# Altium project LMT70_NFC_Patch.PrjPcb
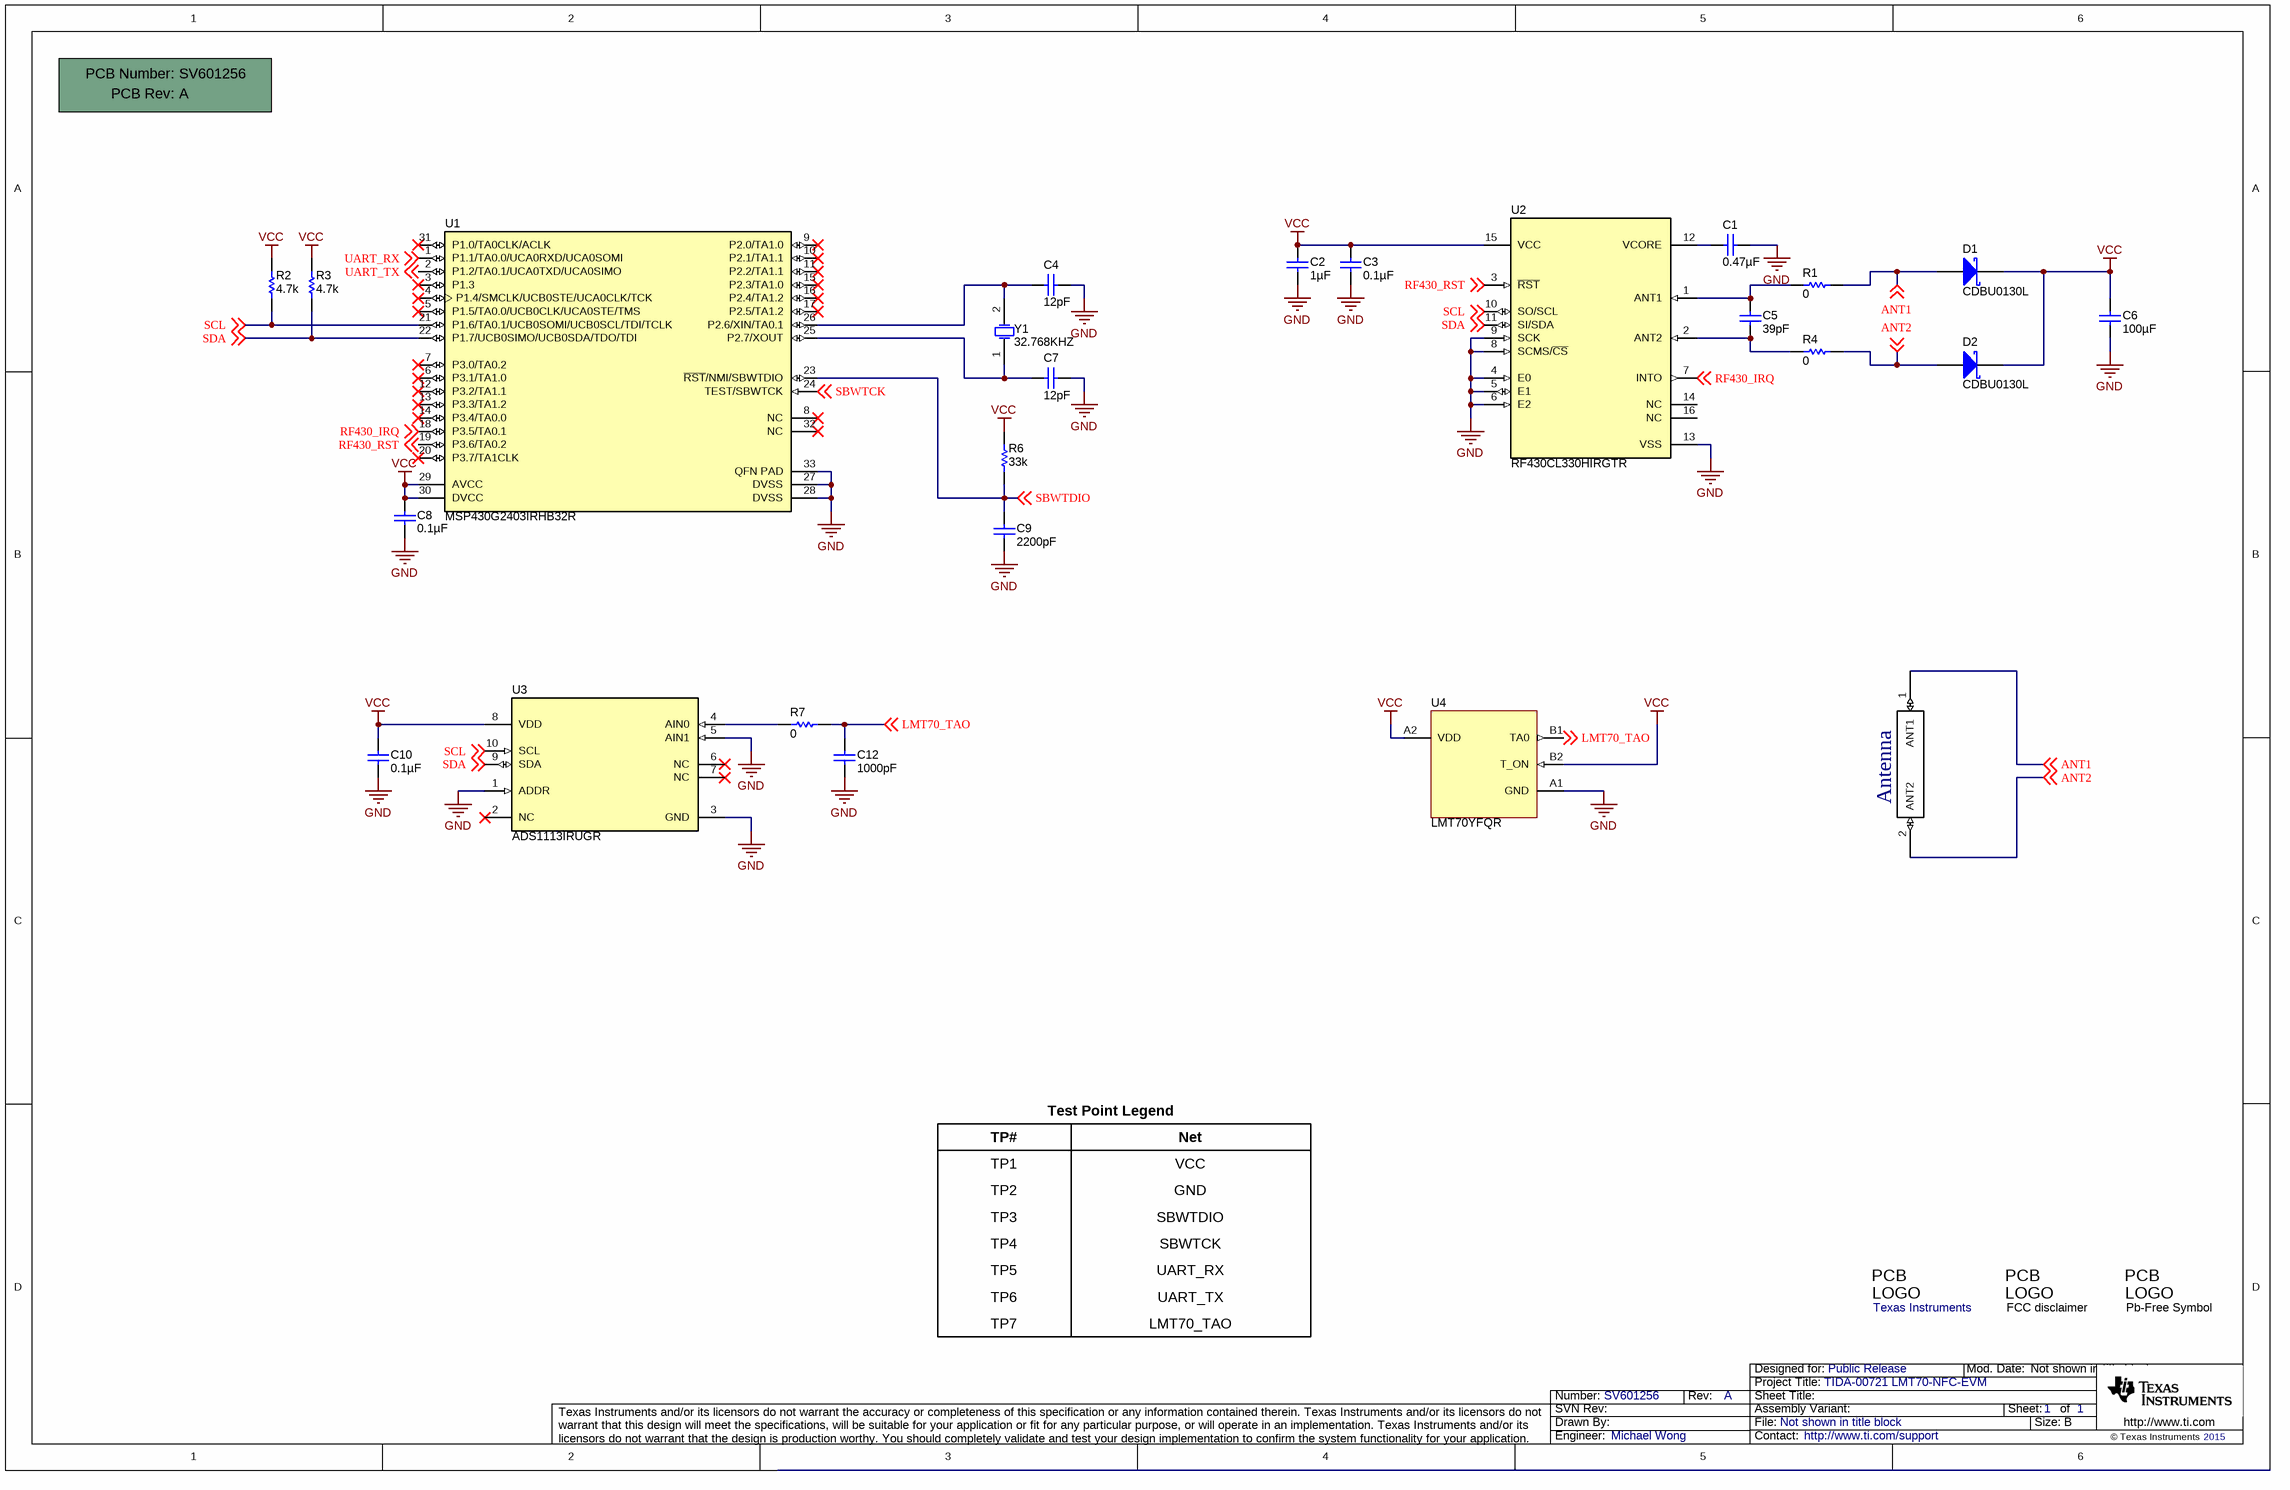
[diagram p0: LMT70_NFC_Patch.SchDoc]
TID: TIDA-00721; TechSupport: http://www.ti.com/support; SCH_Rev: A; PRJ_Title: TIDA-00721 LMT70-NFC-EVM; PRJ_Number: SV601256; PRJ_Engineer: Michael Wong; PRJ_Customer: Public Release; PCB_Rev: A; PCB_Layout: Michael Wong; EVM_Orderable: N/A; CopyrightYear: 2015
1 sheet, 29 parts. Net scope: global (net labels, ports and power ports of the same name join across sheets).
Board file: LMT70_NFC_Patch.PcbDoc

## Sheet LMT70_NFC_Patch.SchDoc
size 431 x 279 mm; Date: Not shown in title block; ApprovedBy: Not shown in title block; CheckedBy: Not shown in title block; Author: Not shown in title block; CompanyName: Not shown in title block; Engineer: Not shown in title block; Organization: Not shown in title block; Address1: Not shown in title block; Address2: Not shown in title block; Address3: Not shown in title block; Address4: Not shown in title block; DocumentNumber: 1; Revision: Use project parameter SCH_Rev; SheetNumber: 1; SheetTotal: 1; PageSetup: Record=PageOptions¦CenterHorizontal=True¦CenterVertical=True¦PrintScale=0.64¦XCorrection=1.00¦YCorrection=1.00¦PrintKind=0¦BorderSize=5000000¦LeftOffset=0¦BottomOffset=0¦Orientation=2¦PaperLength=1000¦PaperWidth=1000¦Scale=100¦PaperSource=15¦PrintQuality=600¦MediaType=1¦DitherType=10¦PaperKind=Letter¦PrintScaleMode=1

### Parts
!PCB  Printed Circuit Board  (value not drawn)  (mechanical)
Antenna_Coil  Antenna Coil  [PCBComponent_1]  (value not drawn)  (no BOM)
C1  ValueDisplayed: 0.47µF  [0402]  (hidden comment: GRM155R61C474KE01)
C2  ValueDisplayed: 1µF  [0402]  (hidden comment: GRM155R61E105KA12D)
C3  ValueDisplayed: 0.1µF  [0402]  (hidden comment: GRM155R61E104KA87D)
C4  ValueDisplayed: 12pF  [0402]  (hidden comment: GRM1555C1E120JA01D)
C5  ValueDisplayed: 39pF  [0402]  (hidden comment: GRM1555C1E390JA01D)
C6  ValueDisplayed: 100µF  [1206_190]  (hidden comment: C3216X5R1A107M160AC)
C7  ValueDisplayed: 12pF  [0402]  (hidden comment: GRM1555C1E120JA01D)
C8  ValueDisplayed: 0.1µF  [0402]  (hidden comment: GRM155R61E104KA87D)
C9  ValueDisplayed: 2200pF  [0402]  (hidden comment: GRM155R71C222KA01D)
C10  ValueDisplayed: 0.1µF  [0402]  (hidden comment: GRM155R61E104KA87D)
C12  ValueDisplayed: 1000pF  [0402]  (hidden comment: GRM155R61E102KA01D)
D1  CDBU0130L  [SOD-523F]
D2  CDBU0130L  [SOD-523F]
Logo1  Pb-Free Symbol  [Pb-Free_Overlay_Medium]  (no BOM)
Logo2  Texas Instruments  [TI_Symbol_Overlay_Small]  (no BOM)
Logo3  FCC disclaimer  [FCC_disclaimer]  (no BOM)
R1  ValueDisplayed: 0  [0402]  (hidden comment: CRCW04020000Z0ED)
R2  ValueDisplayed: 4.7k  [0402]  (hidden comment: CRCW04024K70JNED)
R3  ValueDisplayed: 4.7k  [0402]  (hidden comment: CRCW04024K70JNED)
R4  ValueDisplayed: 0  [0402]  (hidden comment: CRCW04020000Z0ED)
R6  ValueDisplayed: 33k  [0402]  (hidden comment: CRCW040233K0JNED)
R7  ValueDisplayed: 0  [0402]  (hidden comment: CRCW04020000Z0ED)
U1  MSP430G2403IRHB32R  [RHB0032E]
U2  RF430CL330HIRGTR  [RGT0016C]
U3  ADS1113IRUGR  [RUG0010A]
U4  LMT70YFQR  [YFQ0004ACAC]
Y1  Frequency: 32.768KHZ  [Epson_FC-12M]  (hidden comment: FC-12M 32.7680KA-A3)

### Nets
GND: C1.2 C2.2 C3.2 C4.1 C6.2 C7.1 C8.2 C9.2 C10.2 C12.2 U1.27(DVSS) U1.28(DVSS) U1.33(QFN_PAD) U2.4(E0) U2.5(E1) U2.6(E2) U2.8(SCMS/~{CS}) U2.9(SCK) U2.13(VSS) U3.1(ADDR) U3.3(GND) U3.5(AIN1) U4.A1(GND)
VCC: C2.1 C3.1 C6.1 C8.1 C10.1 D1.1(K) D2.1(K) R2.2 R3.2 R6.2 U1.29(AVCC) U1.30(DVCC) U2.15(VCC) U3.8(VDD) U4.A2(VDD) U4.B2(T_ON)
ANT1: Antenna_Coil.1(ANT1) D1.2(A) R1.2 ; off-sheet ANT1
ANT2: Antenna_Coil.2(ANT2) D2.2(A) R4.2 ; off-sheet ANT2
LMT70_TAO: C12.1 R7.2 U4.B1(TA0) ; off-sheet LMT70_TAO
RF430_IRQ: U1.18(P3.5/TA0.1) U2.7(INTO) ; off-sheet RF430_IRQ
RF430_RST: U1.19(P3.6/TA0.2) U2.3(~{RST}) ; off-sheet RF430_RST
SBWTCK: U1.24(TEST/SBWTCK) ; off-sheet SBWTCK
SBWTDIO: C9.1 R6.1 U1.23(~{RST}/NMI/SBWTDIO) ; off-sheet SBWTDIO
SCL: R2.1 U1.21(P1.6/TA0.1/UCB0SOMI/UCB0SCL/TDI/TCLK) U2.10(SO/SCL) U3.10(SCL) ; off-sheet SCL
SDA: R3.1 U1.22(P1.7/UCB0SIMO/UCB0SDA/TDO/TDI) U2.11(SI/SDA) U3.9(SDA) ; off-sheet SDA
UART_RX: U1.1(P1.1/TA0.0/UCA0RXD/UCA0SOMI) ; off-sheet UART_RX
UART_TX: U1.2(P1.2/TA0.1/UCA0TXD/UCA0SIMO) ; off-sheet UART_TX
NetC1_1: C1.1 U2.12(VCORE)
NetC4_2: C4.2 U1.26(P2.6/XIN/TA0.1) Y1.2(OSC2)
NetC5_1: C5.1 R1.1 U2.1(ANT1)
NetC5_2: C5.2 R4.1 U2.2(ANT2)
NetC7_2: C7.2 U1.25(P2.7/XOUT) Y1.1(OSC1)
NetR7_1: R7.1 U3.4(AIN0)

Not connected (* = marked no-connect by the designer): U1 3(P1.3)* 4(P1.4/SMCLK/UCB0STE/UCA0CLK/TCK)* 5(P1.5/TA0.0/UCB0CLK/UCA0STE/TMS)* 6(P3.1/TA1.0)* 7(P3.0/TA0.2)* 8(NC)* 9(P2.0/TA1.0)* 10(P2.1/TA1.1)* 11(P2.2/TA1.1)* 12(P3.2/TA1.1)* 13(P3.3/TA1.2)* 14(P3.4/TA0.0)* 15(P2.3/TA1.0)* 16(P2.4/TA1.2)* 17(P2.5/TA1.2)* 20(P3.7/TA1CLK)* 31(P1.0/TA0CLK/ACLK)* 32(NC)*; U2 14(NC) 16(NC); U3 2(NC)* 6(NC)* 7(NC)*

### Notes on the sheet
- (near Antenna_Coil) Antenna
- TP#
- TP1
- Test Point Legend
- Net
- VCC
- TP2
- TP3
- GND
- SBWTDIO
- TP4
- TP5
- TP6
- SBWTCK
- UART_RX
- UART_TX
- TP7
- LMT70_TAO

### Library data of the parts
!PCB = PCB: Manufacturer: Any; PartNumber: SV601256; SymbolCreator: a0412235
Antenna_Coil = Component_1
C1 = GRM155R61C474KE01: CAP, CERM, 0.47 µF, 16 V, +/- 10%, X5R, 0402; Manufacturer: MuRata; Polarized: N; CompType: Capacitor; Value: 0.47uF; U/M: EA; Cap_F: 0.00000047; Tolerance_%: 10; Value1: Unknown; VDC_V: 16; Value2: 16V; TaMin_C: -55; TaMax_C: 85; AEC Category: Q200
C2 = GRM155R61E105KA12D: CAP, CERM, 1 µF, 25 V, +/- 10%, X5R, 0402; Manufacturer: MuRata; Polarized: N; CompType: Capacitor; Value: 1uF; U/M: EA; Cap_F: 0.000001; Tolerance_%: 10; Value1: Unknown; VDC_V: 25; Value2: 25V; TaMin_C: -55; TaMax_C: 85; AEC Category: Q200
C3 C8 C10 = GRM155R61E104KA87D: CAP, CERM, 0.1 µF, 25 V, +/- 10%, X5R, 0402; Manufacturer: MuRata; Polarized: N; CompType: Capacitor; Value: 0.1uF; U/M: EA; Cap_F: 0.0000001; Tolerance_%: 10; Value1: Unknown; VDC_V: 25; Value2: 25V; TaMin_C: -55; TaMax_C: 85; AEC Category: Q200
C4 C7 = GRM1555C1E120JA01D: CAP, CERM, 12 pF, 25 V, +/- 5%, C0G/NP0, 0402; Manufacturer: MuRata; Polarized: N; CompType: Capacitor; Value: 12pF; U/M: EA; Cap_F: 0.000000000012; Tolerance_%: 5; Value1: Unknown; VDC_V: 25; Value2: 25V; TaMin_C: -55; TaMax_C: 125; AEC Category: Q200
C5 = GRM1555C1E390JA01D: CAP, CERM, 39 pF, 25 V, +/- 5%, C0G/NP0, 0402; Manufacturer: MuRata; Polarized: N; CompType: Capacitor; Value: 39pF; U/M: EA; Cap_F: 0.000000000039; Tolerance_%: 5; Value1: Unknown; VDC_V: 25; Value2: 25V; TaMin_C: -55; TaMax_C: 125; AEC Category: Q200
C6 = C3216X5R1A107M160AC: CAP, CERM, 100 µF, 10 V, +/- 20%, X5R, 1206_190; Manufacturer: TDK; Polarized: N; CompType: Capacitor; Value: 100uF; U/M: EA; Cap_F: 0.0001; Tolerance_%: 20; Value1: Unknown; VDC_V: 10; Value2: 10V; TaMin_C: -55; TaMax_C: 85; Cap_Case: 1206; AEC Category: Q200
C9 = GRM155R71C222KA01D: CAP, CERM, 2200 pF, 16 V, +/- 10%, X7R, 0402; Manufacturer: MuRata; Polarized: N; CompType: Capacitor; Value: 2200pF; U/M: EA; Cap_F: 0.0000000022; Tolerance_%: 10; Value1: Unknown; VDC_V: 16; Value2: 16V; TaMin_C: -55; TaMax_C: 125; AEC Category: Q200
C12 = GRM155R61E102KA01D: CAP, CERM, 1000 pF, 25 V, +/- 10%, X5R, 0402; Manufacturer: MuRata; Polarized: N; CompType: Capacitor; Value: 1000pF; U/M: EA; Cap_F: 0.000000001; Tolerance_%: 10; Value1: Unknown; VDC_V: 25; Value2: 25V; TaMin_C: -55; TaMax_C: 85; AEC Category: Q200
D1 D2 = CDBU0130L: Diode, Schottky, 35 V, 0.1 A, SOD-523F; Manufacturer: Comchip Technology; U/M: EA; Value: 35V; Value1: 0.1A; Io_A: 0.1; Vr_V: 35; TJmax_C: 125; AEC Category: Q101
Logo1 = Pb-Free: SymbolCreator: a0412235
Logo2 = TI_Logo: Texas Instrument Corporate Signature; SymbolCreator: a0412235
Logo3 = FCC_disclaimer: SymbolCreator: codlsc
R1 R4 R7 = CRCW04020000Z0ED: RES, 0, 5%, 0.063 W, 0402; Manufacturer: Vishay-Dale; CompType: Resistor; Value: 0; Value_Code: 0000; Tolerance_%: 5; Power_W: 0.063; Value2: 0.063W; VDC_V: 50; TempCo: 200 ppm/C; EIA_Code: E24; U/M: EA; AEC Category: Q200
R2 R3 = CRCW04024K70JNED: RES, 4.7 k, 5%, 0.063 W, 0402; Manufacturer: Vishay-Dale; CompType: Resistor; Value: 4.7k; Res_ohm: 4700; Value_Code: 4k70; Tolerance_%: 5; Power_W: 0.063; Value2: 0.063W; VDC_V: 50; TempCo: 200 ppm/C; EIA_Code: E24; U/M: EA; AEC Category: Q200
R6 = CRCW040233K0JNED: RES, 33 k, 5%, 0.063 W, 0402; Manufacturer: Vishay-Dale; CompType: Resistor; Value: 33k; Res_ohm: 33000; Value_Code: 33k0; Tolerance_%: 5; Power_W: 0.063; Value2: 0.063W; VDC_V: 50; TempCo: 200 ppm/C; EIA_Code: E24; U/M: EA; AEC Category: Q200
U1 = MSP430G2403IRHB32R: 16 MHz Mixed Signal Microcontroller with 8 KB Flash, 512 B SRAM and 24 GPIOs, -40 to 85 degC, 32-pin QFN (RHB), Green (RoHS & no Sb/Br); Alternate Manufacturer: Texas Instruments; Alternate PartNumber: Equivalent; Brown Out Reset: Yes; Flash(KB): 8; Frequency(MHz): 16; GPIO: 24; Pin/Package: 20PDIP, 20TSSOP, 28TSSOP, 32QFN; SRAM(B): 512; SubFamily: Value Line; Timers - 16-bit: 2; USCI_A (UART/LIN/IrDA/SPI): 1
U2 = RF430CL330HIRGTR: DYNAMIC NFC INTERFACE TRANSPONDER, RGT0016C; Manufacturer: Texas Instruments; SymbolCreator: a0411947; CompType: IC; U/M: EA
U3 = ADS1113IRUGR: Ultra-Small, Low-Power, 16-Bit Analog-to-Digital Converter with Internal Reference, DGS0010A; Alternate PartNumber: ADS1113IRUGT; Manufacturer: Texas Instruments; SymbolCreator: Altium; CompType: IC; U/M: EA
U4 = LMT70YFQR: ±0.1°C Precision Analog Temperature Sensor, RTD and Precision NTC Thermistor IC, YFQ0004ACAC; Alternate PartNumber: LMT70YFQT; Manufacturer: Texas Instruments; SymbolCreator: a0411947; U/M: EA
Y1 = FC-12M 32.7680KA-A3: Crystal, 32.768kHz, 12.5pF, SMD; Manufacturer: Epson; SymbolCreator: a0412235; U/M: EA; TaMin_C: -40; TaMax_C: 85; Frequency Stability: ±20ppm

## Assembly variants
001: not fitted C4 C7 Y1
